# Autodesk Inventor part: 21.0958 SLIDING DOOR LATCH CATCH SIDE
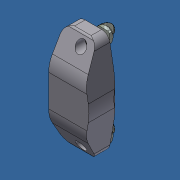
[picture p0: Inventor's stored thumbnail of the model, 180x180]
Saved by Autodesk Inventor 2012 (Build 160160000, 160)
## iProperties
Created: 2014-05
Part Number: 21.0958 SLIDING DOOR LATCH CATCH SIDE
Material: Aluminum-6061
Document SubType Name: Modeling
Designer: Admin
Density: 2.71 g/cm^3
Mass: 134.546 g
Surface Area: 220.758 cm^2
Volume: 49.6478 cm^3
Author: Admin
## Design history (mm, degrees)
node "21.0958 SLIDING DOOR LATCH CATCH SIDE1"
node "Base1"
body "Solid1"
